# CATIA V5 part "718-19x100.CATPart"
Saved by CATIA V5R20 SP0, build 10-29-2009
Part number: 718-19x100
Definition: NONE
Nomenclature: 718-19x100
Source: Unknown
Description: 718-19x100
Bounding box of the stored display mesh (mm): x 0 to 123, y -12.5 to 12.5, z -12.5 to 12.5
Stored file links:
  C:\Users\Utente\Desktop\IO LAVORO\3D X SITO CF\X SITO\718\718-19x100.CATPart

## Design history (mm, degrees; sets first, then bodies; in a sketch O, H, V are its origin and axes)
Body1 "718-19x100" (main body)
  Solid1: solid without history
